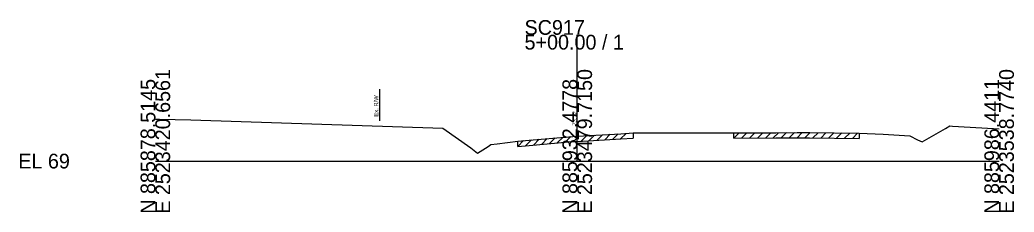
# Model space of a CAD drawing. Extents: x -26 to 218, y -10 to 12021.
# Drawn here: x -25.7 to 162.8, y 4990.3 to 5026.8 of the extents above; entities that cross this region are included whole.
import ezdxf

# ---------------------------------------------------------------- set-up
doc = ezdxf.new("R2010")
doc.units = 0
for name, color, linetype in [('RD_GPK_XS_Cell', 7, 'Continuous'), ('RD_XS_ExGround', 7, 'Continuous'), ('RD_XS_ExPaveRet', 7, 'Continuous'), ('RD_XS_ExRW', 7, 'Continuous'), ('RD_XS_TX_Elev_EX', 7, 'Continuous')]:
    doc.layers.add(name, color=color, linetype=linetype)

msp = doc.modelspace()

# ---------------------------------------------------------------- linework, layer by layer
at = {"layer": 'RD_GPK_XS_Cell'}
for p, q in [((80, 5000), (80, 5023.98)), ((0, 5000), (80, 5000)), ((80, 5000), (160, 5000))]:
    msp.add_line(p, q, dxfattribs=at)
at = {"layer": 'RD_XS_ExGround'}
for p, q in [((0, 5007.99), (0.8, 5007.99)), ((0.8, 5007.99), (6.74, 5007.81)), ((6.74, 5007.81), (54.49, 5006.26)), ((54.49, 5006.26), (59.79, 5002.51)), ((145.38, 5003.64), (149.8, 5006.18)), ((149.8, 5006.18), (150.68, 5006.72)), ((150.68, 5006.72), (151.16, 5006.62)), ((151.16, 5006.62), (158.92, 5006.22)), ((158.92, 5006.22), (160, 5006.13)), ((64.8, 5003.29), (68.71, 5003.8)), ((68.71, 5003.8), (70.89, 5003.98)), ((70.89, 5003.98), (78.43, 5004.63)), ((78.43, 5004.63), (80, 5004.72)), ((80, 5004.72), (88.24, 5005.2)), ((88.24, 5005.2), (90.63, 5005.35)), ((90.63, 5005.35), (96.44, 5005.35)), ((96.44, 5005.35), (99.2, 5005.36)), ((99.2, 5005.36), (104.9, 5005.35)), ((104.9, 5005.35), (109.67, 5005.34)), ((109.67, 5005.34), (117.67, 5005.39)), ((117.67, 5005.39), (121.71, 5005.41)), ((121.71, 5005.41), (124.07, 5005.41)), ((124.07, 5005.41), (133.44, 5005.31)), ((133.44, 5005.31), (138.01, 5005.09)), ((138.01, 5005.09), (143.08, 5004.78)), ((143.08, 5004.78), (144.53, 5004.01)), ((144.53, 5004.01), (145.38, 5003.64)), ((59.79, 5002.51), (61.06, 5001.48)), ((61.06, 5001.48), (63.11, 5002.76)), ((63.11, 5002.76), (63.6, 5003.12)), ((63.6, 5003.12), (64.8, 5003.29))]:
    msp.add_line(p, q, dxfattribs=at)
at = {"layer": 'RD_XS_ExPaveRet'}
for p, q in [((68.71, 5002.8), (69.8, 5003.89)), ((68.71, 5002.8), (68.71, 5003.8)), ((70.21, 5002.93), (71.3, 5004.02)), ((71.71, 5003.05), (72.8, 5004.15)), ((73.21, 5003.18), (74.3, 5004.28)), ((74.71, 5003.31), (75.8, 5004.4)), ((76.21, 5003.44), (77.3, 5004.53)), ((77.71, 5003.57), (78.79, 5004.65)), ((78.43, 5003.63), (80, 5003.72)), ((79.21, 5003.68), (80.27, 5004.74)), ((80, 5003.72), (88.24, 5004.2)), ((80.71, 5003.76), (81.77, 5004.82)), ((82.21, 5003.85), (83.27, 5004.91)), ((83.71, 5003.94), (84.77, 5005)), ((85.21, 5004.02), (86.27, 5005.09)), ((86.71, 5004.11), (87.77, 5005.17)), ((88.21, 5004.2), (89.28, 5005.26)), ((88.24, 5004.2), (90.63, 5004.35)), ((90.63, 5005.35), (90.63, 5004.35)), ((109.67, 5004.34), (110.68, 5005.35)), ((109.67, 5004.34), (109.67, 5005.34)), ((109.67, 5004.34), (117.67, 5004.39)), ((111.17, 5004.35), (112.18, 5005.36)), ((112.67, 5004.36), (113.68, 5005.37)), ((114.17, 5004.37), (115.18, 5005.38)), ((115.67, 5004.38), (116.68, 5005.39)), ((117.17, 5004.39), (118.18, 5005.39)), ((117.67, 5004.39), (121.71, 5004.41)), ((118.67, 5004.39), (119.67, 5005.4)), ((120.17, 5004.4), (121.17, 5005.4)), ((121.67, 5004.4), (122.67, 5005.41)), ((121.71, 5004.41), (124.07, 5004.41)), ((123.17, 5004.41), (124.17, 5005.41)), ((124.07, 5004.41), (133.44, 5004.31)), ((124.67, 5004.4), (125.66, 5005.39)), ((126.17, 5004.38), (127.16, 5005.37)), ((127.67, 5004.37), (128.66, 5005.36)), ((129.17, 5004.35), (130.16, 5005.34)), ((130.67, 5004.34), (131.66, 5005.32)), ((132.17, 5004.32), (133.16, 5005.31)), ((133.44, 5005.31), (133.44, 5004.31)), ((68.71, 5002.8), (70.89, 5002.98)), ((70.89, 5002.98), (78.43, 5003.63))]:
    msp.add_line(p, q, dxfattribs=at)
at = {"layer": 'RD_XS_ExRW'}
msp.add_line((42.5, 5013.65), (42.5, 5007.65), dxfattribs=at)

# ---------------------------------------------------------------- texts
at = {"layer": 'RD_GPK_XS_Cell'}
for s, p in [('SC917', (70, 5023.98)), ('5+00.00 / 1', (70, 5021.18)), ('EL 69', (-26, 4998.6))]:
    msp.add_text(s, height=2.8, dxfattribs=at).set_placement(p)
for s, p in [('E 2523420.6561', (2.8, 4990)), ('E 2523479.7150', (82.8, 4990)), ('E 2523538.7740', (162.8, 4990)), ('N 885878.5145', (0, 4990)), ('N 885932.4778', (80, 4990)), ('N 885986.4411', (160, 4990))]:
    msp.add_text(s, height=2.8, rotation=90, dxfattribs=at).set_placement(p)
at = {"layer": 'RD_XS_ExRW'}
msp.add_text('Ex. R/W ', height=0.8, rotation=90, dxfattribs=at).set_placement((42.25, 5008.44))
at = {"layer": 'RD_XS_TX_Elev_EX'}
msp.add_text('73.72', height=0.8, rotation=90, dxfattribs=at).set_placement((79.9, 5006.72))

doc.saveas('drawing.dxf')
